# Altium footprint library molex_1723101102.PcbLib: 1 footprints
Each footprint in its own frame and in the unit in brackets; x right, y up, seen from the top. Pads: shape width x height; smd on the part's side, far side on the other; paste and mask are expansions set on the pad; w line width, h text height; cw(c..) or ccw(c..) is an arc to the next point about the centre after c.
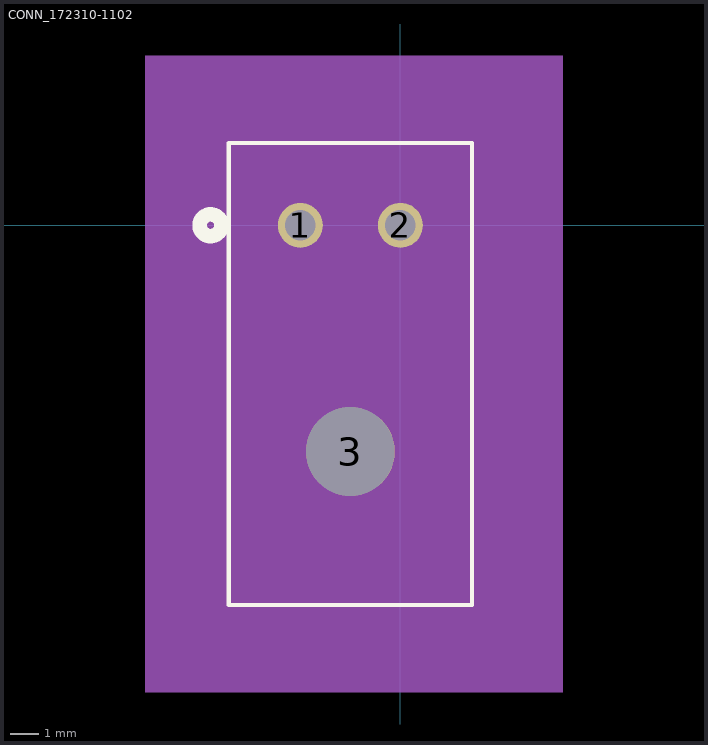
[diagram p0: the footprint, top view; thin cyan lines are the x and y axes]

## CONN_172310-1102 [mil]
pads (3):
  round 62 hole 42 mask+0: 1(-137.8,0) 2(0,0)
  round 122 hole 122: 3(-68.9,-311.42)
Top Overlay:
  circle w20: c-261.4,0 r15
  lines w6: -236.4,-522.73 98.6,-522.73 98.6,113.27 -236.4,113.27 -236.4,-522.73
Bottom Overlay:
  circle w20: c-261.4,0 r15
Mechanical 5:
  region: -351.4,233.27 223.6,233.27 223.6,-642.73 -351.4,-642.73
Mechanical 13:
  circle w20: c-137.8,-75 r15
  lines w1: -231.4,-517.73 93.6,-517.73 93.6,108.27 -231.4,108.27 -231.4,-517.73
Mechanical 15:
  region: 103.6,118.27 -241.4,118.27 -241.4,-527.73 103.6,-527.73
  lines w6: -241.4,-527.73 -241.4,118.27 103.6,118.27 103.6,-527.73 -241.4,-527.73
